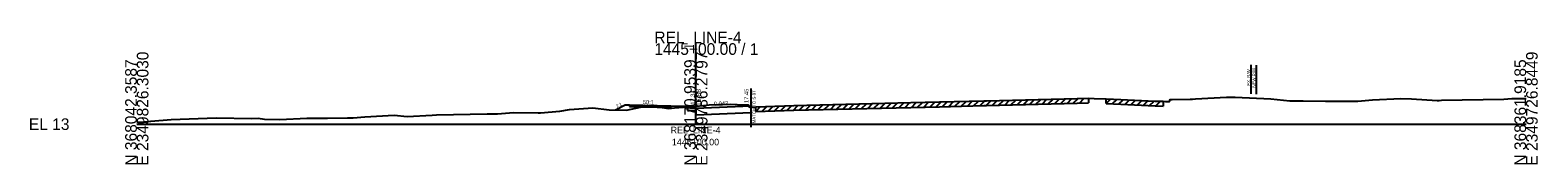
# Model space of a CAD drawing. Extents: x -26 to 2350146, y -10 to 368200.
# Drawn here: x 1974.3 to 2337.5, y 5490.3 to 5522.3 of the extents above; entities that cross this region are included whole.
import ezdxf

# ---------------------------------------------------------------- set-up
doc = ezdxf.new("R2010")
doc.units = 0
for name, color, linetype in [('RD_GPK_XS_Cell', 7, 'Continuous'), ('RD_XS_Base', 7, 'Continuous'), ('RD_XS_CurbBase', 7, 'Continuous'), ('RD_XS_CurbFront', 7, 'Continuous'), ('RD_XS_CurbTop', 7, 'Continuous'), ('RD_XS_EarthShd', 7, 'Continuous'), ('RD_XS_ExGround', 7, 'Continuous'), ('RD_XS_ExPaveRet', 7, 'Continuous'), ('RD_XS_ExRW', 7, 'Continuous'), ('RD_XS_NewRW', 7, 'Continuous'), ('RD_XS_Pave', 7, 'Continuous'), ('RD_XS_SW', 7, 'Continuous'), ('RD_XS_SWbase', 7, 'Continuous'), ('RD_XS_TieSlope', 7, 'Continuous'), ('RD_XS_TX_Elev_EX', 7, 'Continuous'), ('RD_XS_TX_Elev_PR', 7, 'Continuous'), ('RD_XS_TX_MatchLine', 7, 'Continuous'), ('RD_XS_TX_Slope', 7, 'Continuous'), ('RD_XS_TX_Station', 7, 'Continuous'), ('RD_XS_TX_TOC', 7, 'Continuous')]:
    doc.layers.add(name, color=color, linetype=linetype)

msp = doc.modelspace()

# ---------------------------------------------------------------- linework, layer by layer
at = {"layer": 'RD_GPK_XS_Cell'}
for p, q in [((2134.68, 5500), (2134.68, 5519.5)), ((2000, 5500), (2134.68, 5500)), ((2134.68, 5500), (2334.68, 5500))]:
    msp.add_line(p, q, dxfattribs=at)
at = {"layer": 'RD_XS_Base'}
msp.add_line((2134.68, 5502.24), (2147.96, 5502.81), dxfattribs=at)
at = {"layer": 'RD_XS_CurbBase'}
for p, q in [((2132.68, 5504.27), (2132.68, 5503.27)), ((2132.68, 5503.27), (2133.18, 5503.27)), ((2133.18, 5503.27), (2134.68, 5503.35)), ((2134.68, 5502.24), (2134.68, 5503.35))]:
    msp.add_line(p, q, dxfattribs=at)
at = {"layer": 'RD_XS_CurbFront'}
msp.add_line((2134.68, 5503.35), (2134.68, 5503.85), dxfattribs=at)
at = {"layer": 'RD_XS_CurbTop'}
for p, q in [((2133.18, 5504.27), (2132.68, 5504.27)), ((2133.26, 5503.77), (2133.18, 5504.27)), ((2134.68, 5503.85), (2133.26, 5503.77)), ((2134.68, 5503.88), (2134.68, 5503.85))]:
    msp.add_line(p, q, dxfattribs=at)
at = {"layer": 'RD_XS_EarthShd'}
for p, q in [((2118.68, 5504.55), (2117.68, 5504.57)), ((2132.68, 5504.27), (2128.68, 5504.35))]:
    msp.add_line(p, q, dxfattribs=at)
at = {"layer": 'RD_XS_ExGround'}
msp.add_lwpolyline([(2000, 5500.52), (2001.77, 5500.57), (2002.28, 5500.53), (2003.36, 5500.69), (2008.25, 5501.14), (2019.15, 5501.52), (2027.71, 5501.4), (2029.22, 5501.41), (2030.8, 5501.2), (2034.48, 5501.11), (2040.93, 5501.48), (2045.96, 5501.48), (2050.75, 5501.49), (2052.1, 5501.49), (2054.94, 5501.74), (2062.01, 5502.15), (2065.16, 5501.87), (2071.15, 5502.19), (2072.22, 5502.27), (2084.43, 5502.47), (2086.9, 5502.49), (2090.73, 5502.81), (2096.71, 5502.74), (2097.22, 5502.76), (2101.94, 5503.13), (2104.2, 5503.51), (2109.84, 5503.96), (2113.81, 5503.42), (2117.95, 5503.4), (2121.31, 5504.06), (2122.91, 5504.2), (2124.39, 5504.3), (2126.09, 5504.1), (2128.08, 5503.76), (2129.52, 5503.94), (2131.72, 5504.08), (2134.68, 5504.34), (2136.55, 5504.5), (2137.9, 5504.64), (2139.96, 5504.71), (2141.12, 5504.75), (2143.04, 5504.78), (2146.34, 5504.65), (2146.79, 5504.65), (2147.32, 5504.64), (2147.49, 5504.13), (2149.09, 5504.19), (2158.3, 5504.48), (2186.44, 5505.19), (2193.38, 5505.35), (2204.07, 5505.61), (2204.68, 5505.63), (2226.52, 5506.19), (2229.27, 5506.26), (2230.64, 5506.22), (2233.5, 5506.13), (2237.05, 5505.92), (2240.35, 5505.76), (2245.31, 5505.57), (2247.28, 5505.52), (2247.78, 5505.49), (2248.79, 5505.44), (2248.95, 5505.94), (2249.45, 5505.94), (2253.78, 5506.04), (2254.29, 5506.05), (2255.03, 5506.12), (2262.5, 5506.5), (2264.6, 5506.48), (2273.17, 5506.07), (2277.77, 5505.62), (2280.99, 5505.66), (2286.35, 5505.54), (2291.03, 5505.52), (2294.13, 5505.54), (2297.67, 5505.9), (2304.48, 5506.17), (2307.11, 5506.08), (2313.25, 5505.73), (2313.75, 5505.72), (2314.34, 5505.75), (2329.36, 5506.04), (2331.29, 5506.15), (2334.68, 5506.2)], dxfattribs=at)
at = {"layer": 'RD_XS_ExPaveRet'}
for p, q in [((2149.09, 5503.04), (2150.27, 5504.23)), ((2149.09, 5503.04), (2149.09, 5504.19)), ((2149.09, 5503.04), (2158.3, 5503.34)), ((2150.59, 5503.09), (2151.77, 5504.27)), ((2152.09, 5503.14), (2153.27, 5504.32)), ((2153.59, 5503.19), (2154.77, 5504.37)), ((2155.09, 5503.24), (2156.27, 5504.42)), ((2156.59, 5503.28), (2157.77, 5504.47)), ((2158.09, 5503.33), (2159.26, 5504.51)), ((2158.3, 5503.34), (2186.44, 5504.04)), ((2159.59, 5503.37), (2160.76, 5504.54)), ((2161.09, 5503.41), (2162.26, 5504.58)), ((2162.59, 5503.45), (2163.76, 5504.62)), ((2164.09, 5503.48), (2165.26, 5504.66)), ((2165.59, 5503.52), (2166.76, 5504.69)), ((2167.09, 5503.56), (2168.26, 5504.73)), ((2168.59, 5503.6), (2169.76, 5504.77)), ((2170.09, 5503.63), (2171.26, 5504.81)), ((2171.59, 5503.67), (2172.76, 5504.84)), ((2173.09, 5503.71), (2174.26, 5504.88)), ((2174.59, 5503.75), (2175.76, 5504.92)), ((2176.09, 5503.78), (2177.26, 5504.96)), ((2177.59, 5503.82), (2178.76, 5504.99)), ((2179.09, 5503.86), (2180.26, 5505.03)), ((2180.59, 5503.9), (2181.76, 5505.07)), ((2182.09, 5503.93), (2183.26, 5505.11)), ((2183.59, 5503.97), (2184.76, 5505.14)), ((2185.09, 5504.01), (2186.26, 5505.18)), ((2186.44, 5504.04), (2193.38, 5504.21)), ((2186.59, 5504.05), (2187.76, 5505.22)), ((2188.09, 5504.08), (2189.26, 5505.25)), ((2189.59, 5504.12), (2190.76, 5505.29)), ((2191.09, 5504.15), (2192.26, 5505.32)), ((2192.59, 5504.19), (2193.76, 5505.36)), ((2193.38, 5504.21), (2204.07, 5504.47)), ((2194.09, 5504.22), (2195.26, 5505.4)), ((2195.59, 5504.26), (2196.76, 5505.43)), ((2197.09, 5504.3), (2198.26, 5505.47)), ((2198.59, 5504.33), (2199.76, 5505.5)), ((2200.09, 5504.37), (2201.26, 5505.54)), ((2201.59, 5504.41), (2202.76, 5505.58)), ((2203.09, 5504.44), (2204.26, 5505.61)), ((2204.07, 5504.47), (2204.68, 5504.48)), ((2204.59, 5504.48), (2205.76, 5505.65)), ((2204.68, 5504.48), (2226.52, 5505.05)), ((2206.09, 5504.52), (2207.26, 5505.69)), ((2207.59, 5504.56), (2208.76, 5505.73)), ((2209.09, 5504.6), (2210.26, 5505.77)), ((2210.59, 5504.63), (2211.76, 5505.81)), ((2212.09, 5504.67), (2213.26, 5505.85)), ((2213.59, 5504.71), (2214.76, 5505.89)), ((2215.09, 5504.75), (2216.26, 5505.92)), ((2216.59, 5504.79), (2217.76, 5505.96)), ((2218.09, 5504.83), (2219.26, 5506)), ((2219.59, 5504.87), (2220.76, 5506.04)), ((2221.09, 5504.91), (2222.26, 5506.08)), ((2222.59, 5504.94), (2223.76, 5506.12)), ((2224.09, 5504.98), (2225.26, 5506.16)), ((2225.59, 5505.02), (2226.76, 5506.2)), ((2226.52, 5505.05), (2229.27, 5505.12)), ((2227.09, 5505.06), (2228.26, 5506.23)), ((2229.27, 5506.26), (2229.27, 5505.12)), ((2233.5, 5504.98), (2233.5, 5506.13)), ((2233.5, 5504.98), (2234.58, 5506.06)), ((2233.5, 5504.98), (2237.05, 5504.78)), ((2235, 5504.9), (2236.08, 5505.98)), ((2236.5, 5504.81), (2237.59, 5505.89)), ((2237.05, 5504.78), (2240.35, 5504.62)), ((2238, 5504.73), (2239.09, 5505.82)), ((2239.5, 5504.66), (2240.59, 5505.76)), ((2240.35, 5504.62), (2245.31, 5504.43)), ((2241, 5504.6), (2242.1, 5505.7)), ((2242.5, 5504.54), (2243.6, 5505.64)), ((2244, 5504.48), (2245.1, 5505.58)), ((2245.31, 5504.43), (2247.28, 5504.37)), ((2245.5, 5504.42), (2246.61, 5505.54)), ((2247.28, 5505.52), (2247.28, 5504.37))]:
    msp.add_line(p, q, dxfattribs=at)
at = {"layer": 'RD_XS_ExRW'}
msp.add_line((2268.49, 5507.3), (2268.49, 5514.3), dxfattribs=at)
at = {"layer": 'RD_XS_NewRW'}
msp.add_line((2269.76, 5507.24), (2269.76, 5514.24), dxfattribs=at)
at = {"layer": 'RD_XS_Pave'}
for p, q in [((2147.96, 5508.63), (2147.96, 5499.31)), ((2134.68, 5503.88), (2147.96, 5504.45))]:
    msp.add_line(p, q, dxfattribs=at)
at = {"layer": 'RD_XS_SW'}
msp.add_line((2128.68, 5504.35), (2118.68, 5504.55), dxfattribs=at)
at = {"layer": 'RD_XS_SWbase'}
for p, q in [((2118.68, 5504.55), (2118.68, 5504.22)), ((2118.68, 5504.22), (2128.68, 5504.02)), ((2128.68, 5504.02), (2128.68, 5504.35))]:
    msp.add_line(p, q, dxfattribs=at)
at = {"layer": 'RD_XS_TieSlope'}
msp.add_line((2117.68, 5504.57), (2115.35, 5503.41), dxfattribs=at)

# ---------------------------------------------------------------- texts
at = {"layer": 'RD_GPK_XS_Cell'}
for s, p in [('REL_LINE-4', (2124.68, 5519.5)), ('1445+00.00 / 1', (2124.68, 5516.7)), ('EL 13', (1974, 5498.6))]:
    msp.add_text(s, height=2.8, dxfattribs=at).set_placement(p)
for s, p in [('E 2349826.3030', (2002.8, 5490)), ('E 2349786.2797', (2137.48, 5490)), ('E 2349726.8449', (2337.48, 5490)), ('N 368042.3587', (2000, 5490)), ('N 368170.9539', (2134.68, 5490)), ('N 368361.9185', (2334.68, 5490))]:
    msp.add_text(s, height=2.8, rotation=90, dxfattribs=at).set_placement(p)
at = {"layer": 'RD_XS_ExRW'}
msp.add_text('EX. R/W ', height=0.75, rotation=90, dxfattribs=at).set_placement((2268.24, 5509.25))
at = {"layer": 'RD_XS_NewRW'}
msp.add_text('NEW R/W ', height=0.75, rotation=90, dxfattribs=at).set_placement((2269.51, 5508.82))
at = {"layer": 'RD_XS_TX_Elev_EX'}
msp.add_text('17.34', height=1, rotation=90, dxfattribs=at).set_placement((2134.4, 5504.67))
at = {"layer": 'RD_XS_TX_Elev_PR'}
for s, height, rotation, p in [(' 16.88', 1.2, 90, (2135.88, 5503.88)), ('17.45', 1, 90, (2147.35, 5505.1)), ('50:1', 1, 358.8542, (2121.89, 5504.83)), ('0.043', 1, 2.4622, (2139.04, 5504.4))]:
    msp.add_text(s, height=height, rotation=rotation, dxfattribs=at).set_placement(p)
at = {"layer": 'RD_XS_TX_MatchLine'}
msp.add_text('MATCH TO S-97', height=0.75, rotation=90, dxfattribs=at).set_placement((2149.07, 5500.22))
at = {"layer": 'RD_XS_TX_Slope'}
msp.add_text('2:1', height=0.75, rotation=26.5651, dxfattribs=at).set_placement((2115.65, 5503.95))
at = {"layer": 'RD_XS_TX_Station'}
for s, p in [('REL_LINE-4', (2128.61, 5497.78)), ('1445+00.00', (2128.91, 5494.88))]:
    msp.add_text(s, height=1.6, dxfattribs=at).set_placement(p)
at = {"layer": 'RD_XS_TX_TOC'}
msp.add_text('TOCLT', height=0.05, dxfattribs=at).set_placement((2133.23, 5504.22))

doc.saveas('drawing.dxf')
